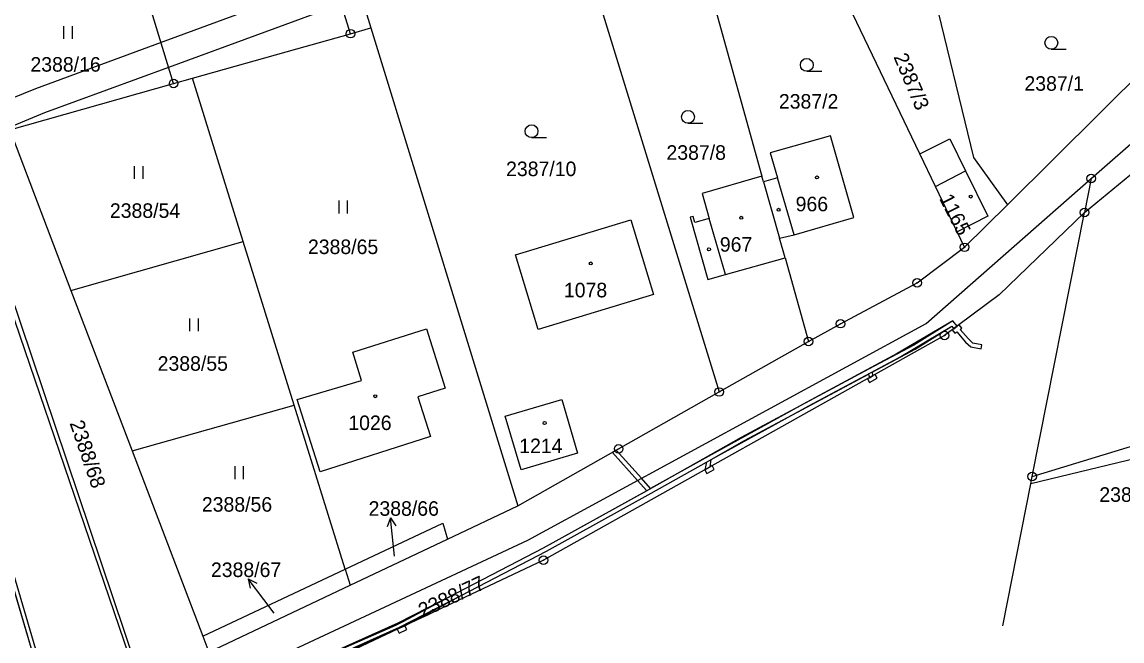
# Model space of a CAD drawing. Extents: x -758836 to -757729, y -1175316 to -1174366.
# Drawn here: x -758454.3 to -758325.7, y -1175183.4 to -1175111 of the extents above; entities that cross this region are included whole.
import ezdxf

# ---------------------------------------------------------------- set-up
doc = ezdxf.new("R2010")
doc.units = 0
for name, color, linetype in [('Hranice parcel', 7, 'Continuous'), ('Parcelní čísla', 7, 'Continuous'), ('Pop  PČ popisy', 7, 'Continuous'), ('Vnitřní kresba', 7, 'Continuous'), ('Věcná břemena k části', 7, 'Continuous'), ('Značky bodu BP', 7, 'Continuous'), ('Značky budov', 7, 'Continuous'), ('Značky kultur', 7, 'Continuous')]:
    doc.layers.add(name, color=color, linetype=linetype)

msp = doc.modelspace()

# ---------------------------------------------------------------- linework, layer by layer
at = {"layer": 'Hranice parcel'}
for p, q in [((-758415.92, -1175112.41), (-758425.55, -1175080.99)), ((-758375.8, -1175100.38), (-758367.83, -1175129.06)), ((-758349.38, -1175126.44), (-758360.76, -1175102.68)), ((-758388.61, -1175102.92), (-758372.81, -1175154.29)), ((-758414.64, -1175108.08), (-758413.52, -1175111.73)), ((-758415.92, -1175112.41), (-758413.52, -1175111.73)), ((-758413.52, -1175111.73), (-758396.34, -1175167.59)), ((-758339.13, -1175132.41), (-758318.22, -1175111.63)), ((-758436.59, -1175118.23), (-758434.39, -1175117.61)), ((-758428.45, -1175136.72), (-758434.39, -1175117.61)), ((-758329.33, -1175129.34), (-758316.55, -1175118.12)), ((-758455.74, -1175123.64), (-758436.59, -1175118.23)), ((-758330.11, -1175133.3), (-758315.7, -1175121.4)), ((-758455.74, -1175123.64), (-758448.59, -1175142.41)), ((-758359.8, -1175124.34), (-758366.84, -1175126.35)), ((-758461.57, -1175125.29), (-758440.3, -1175188.4)), ((-758367.83, -1175129.06), (-758374.82, -1175131.1)), ((-758367.64, -1175129.74), (-758367.83, -1175129.06)), ((-758367.64, -1175129.74), (-758365.77, -1175136.32)), ((-758329.33, -1175129.34), (-758330.11, -1175133.3)), ((-758344.14, -1175137.38), (-758339.13, -1175132.41)), ((-758336.22, -1175164.17), (-758330.11, -1175133.3)), ((-758344.14, -1175137.38), (-758345.01, -1175135.56)), ((-758448.59, -1175142.41), (-758428.45, -1175136.72)), ((-758422.5, -1175155.82), (-758428.45, -1175136.72)), ((-758365.12, -1175138.6), (-758365.77, -1175136.32)), ((-758365.12, -1175138.6), (-758362.37, -1175148.39)), ((-758448.59, -1175142.41), (-758441.44, -1175161.17)), ((-758372.81, -1175154.29), (-758362.37, -1175148.39)), ((-758336.22, -1175164.17), (-758306.97, -1175155.26)), ((-758441.44, -1175161.17), (-758422.5, -1175155.82)), ((-758416.54, -1175174.99), (-758422.5, -1175155.82)), ((-758307.4, -1175158), (-758336.39, -1175165.01)), ((-758441.44, -1175161.17), (-758433.19, -1175182.83)), ((-758336.39, -1175165.01), (-758336.22, -1175164.17)), ((-758339.68, -1175181.63), (-758336.39, -1175165.01)), ((-758404.56, -1175171.48), (-758396.34, -1175167.59)), ((-758415.95, -1175176.88), (-758404.56, -1175171.48)), ((-758433.19, -1175182.83), (-758416.54, -1175174.99)), ((-758416.54, -1175174.99), (-758415.95, -1175176.88)), ((-758432.48, -1175184.7), (-758415.95, -1175176.88)), ((-758433.19, -1175182.83), (-758432.48, -1175184.7))]:
    msp.add_line(p, q, dxfattribs=at)
for points in [[(-758436.59, -1175118.23), (-758442.14, -1175100.06), (-758445.89, -1175087.81)], [(-758347.9, -1175107.11), (-758343.08, -1175126.87), (-758339.13, -1175132.41)], [(-758434.39, -1175117.61), (-758422.18, -1175114.17), (-758415.92, -1175112.41)], [(-758365.77, -1175136.32), (-758364.07, -1175135.91), (-758357.09, -1175133.9), (-758359.8, -1175124.34)], [(-758440.6, -1175188.57), (-758462.14, -1175125.6), (-758461.57, -1175125.29)], [(-758349.38, -1175126.44), (-758345.87, -1175124.7), (-758344.02, -1175128.45), (-758341.4, -1175133.73), (-758345.01, -1175135.56)], [(-758366.84, -1175126.35), (-758366, -1175129.25), (-758367.64, -1175129.74)], [(-758345.01, -1175135.56), (-758347.55, -1175130.26), (-758349.38, -1175126.44)], [(-758452.3, -1175199.04), (-758446.3, -1175195.5), (-758395.2, -1175171.61), (-758348.62, -1175146.28), (-758329.33, -1175129.34)], [(-758374.82, -1175131.1), (-758373.98, -1175134), (-758375.65, -1175134.48), (-758375.86, -1175133.77), (-758376.2, -1175133.86), (-758374.15, -1175141.14), (-758372.09, -1175140.56), (-758365.12, -1175138.6)], [(-758330.11, -1175133.3), (-758340.08, -1175142.92), (-758346.47, -1175147.7), (-758393.35, -1175173.94), (-758437.3, -1175194.73), (-758452.3, -1175199.04)], [(-758380.51, -1175142.9), (-758393.97, -1175146.99), (-758396.61, -1175138.25), (-758383.14, -1175134.16), (-758380.51, -1175142.9)], [(-758362.37, -1175148.39), (-758358.63, -1175146.31), (-758349.68, -1175141.53), (-758344.14, -1175137.38)], [(-758408.05, -1175154.84), (-758406.58, -1175159.49), (-758419.48, -1175163.61), (-758422.14, -1175155.17), (-758414.61, -1175152.93), (-758415.66, -1175149.63), (-758407.02, -1175146.89), (-758404.85, -1175153.83), (-758408.05, -1175154.84)], [(-758389.38, -1175161.44), (-758395.98, -1175163.4), (-758397.84, -1175157.12), (-758391.23, -1175155.18), (-758389.38, -1175161.44)], [(-758396.34, -1175167.59), (-758384.57, -1175160.94), (-758372.81, -1175154.29)], [(-758458.25, -1175167.38), (-758452.99, -1175185.19), (-758456.12, -1175193.18)], [(-758416.54, -1175174.99), (-758405.13, -1175169.62), (-758404.56, -1175171.48)]]:
    msp.add_lwpolyline(points, dxfattribs=at)
at = {"layer": 'Pop  PČ popisy'}
for p, q in [((-758411.22, -1175169.01), (-758411.62, -1175170.05)), ((-758410.91, -1175171.99), (-758411.22, -1175169.01)), ((-758411.22, -1175169.01), (-758410.62, -1175169.95)), ((-758410.77, -1175173.5), (-758410.91, -1175171.99)), ((-758426.06, -1175178.54), (-758427.87, -1175176.14)), ((-758427.87, -1175176.14), (-758426.86, -1175176.64)), ((-758427.87, -1175176.14), (-758427.66, -1175177.24)), ((-758424.83, -1175180.15), (-758426.06, -1175178.54))]:
    msp.add_line(p, q, dxfattribs=at)
at = {"layer": 'Vnitřní kresba'}
for p, q in [((-758347.55, -1175130.26), (-758344.02, -1175128.45)), ((-758364.07, -1175135.91), (-758366, -1175129.25)), ((-758372.09, -1175140.56), (-758373.98, -1175134))]:
    msp.add_line(p, q, dxfattribs=at)
at = {"layer": 'Věcná břemena k části'}
for points in [[(-758456.92, -1175120.55), (-758455.85, -1175123.36), (-758451.64, -1175121.64), (-758437.17, -1175116.34), (-758416.98, -1175108.94), (-758417.89, -1175105.98), (-758438.06, -1175113.43), (-758452.72, -1175118.84)], [(-758344.99, -1175146.59), (-758345.39, -1175146.89), (-758345.59, -1175147.04), (-758345.26, -1175147.43), (-758345.05, -1175147.27), (-758344.01, -1175148.47), (-758343.4, -1175149.03), (-758342.21, -1175149.26), (-758342.11, -1175148.77), (-758343.15, -1175148.57), (-758343.73, -1175148.05), (-758344.66, -1175146.97), (-758344.46, -1175146.82), (-758344.78, -1175146.44)], [(-758354.59, -1175152.25), (-758354.82, -1175152.37), (-758355.26, -1175152.62), (-758355.47, -1175152.74), (-758355.23, -1175153.17), (-758354.35, -1175152.69)], [(-758373.39, -1175163.35), (-758373.63, -1175162.9), (-758373.86, -1175163.03), (-758374.51, -1175163.39), (-758374.27, -1175163.83)], [(-758410.46, -1175182.03), (-758410.24, -1175182.49), (-758409.34, -1175182.05), (-758409.56, -1175181.61)]]:
    msp.add_lwpolyline(points, close=True, dxfattribs=at)
for points in [[(-758452.51, -1175185.05), (-758457.77, -1175167.24), (-758464.65, -1175143.99), (-758470.26, -1175124.61), (-758471.23, -1175121.5), (-758471.28, -1175120.18), (-758472.1, -1175120.53), (-758473.1, -1175120.87), (-758472.98, -1175121.3), (-758472.94, -1175121.45), (-758471.91, -1175121.17), (-758465.13, -1175144.13), (-758458.36, -1175167), (-758459.47, -1175167.31), (-758459.3, -1175167.95), (-758459.26, -1175168.08), (-758458.14, -1175167.76), (-758452.99, -1175185.19)], [(-758426.42, -1175189.06), (-758410.18, -1175181.77), (-758402.97, -1175178.06), (-758393.01, -1175172.91), (-758380.76, -1175166.13), (-758374.3, -1175162.51), (-758373.75, -1175162.2), (-758362.35, -1175155.92), (-758351.76, -1175150.25), (-758345.62, -1175146.61), (-758345.39, -1175146.89), (-758344.99, -1175146.59), (-758345.52, -1175145.97), (-758352, -1175149.81), (-758362.59, -1175155.48), (-758374.1, -1175161.82), (-758380.83, -1175165.59), (-758381.91, -1175164.38), (-758384.85, -1175161.1), (-758385.29, -1175161.35), (-758382.36, -1175164.63), (-758381.28, -1175165.84), (-758393.39, -1175172.55), (-758403.45, -1175177.75), (-758410.4, -1175181.31), (-758426.7, -1175188.64)], [(-758426.42, -1175189.06), (-758410.46, -1175182.03), (-758409.56, -1175181.61), (-758402.97, -1175178.06), (-758393.01, -1175172.91), (-758380.76, -1175166.13), (-758374.3, -1175162.51), (-758374.51, -1175163.39), (-758373.86, -1175163.03), (-758373.75, -1175162.2), (-758369.86, -1175159.96), (-758355.38, -1175152.22), (-758355.26, -1175152.62), (-758354.82, -1175152.37), (-758354.93, -1175151.98), (-758349.9, -1175149.28), (-758345.62, -1175146.61), (-758345.39, -1175146.89), (-758344.99, -1175146.59), (-758345.52, -1175145.97), (-758350.06, -1175148.8), (-758355.35, -1175151.64), (-758370.26, -1175159.6), (-758381, -1175165.69), (-758393.39, -1175172.55), (-758403.45, -1175177.75), (-758409.8, -1175181.17), (-758410.66, -1175181.57), (-758426.7, -1175188.64)]]:
    msp.add_lwpolyline(points, dxfattribs=at)
at = {"layer": 'Značky bodu BP'}
for centre, radius in [((-758415.92, -1175112.41), 0.5), ((-758415.92, -1175112.41), 0.0303), ((-758436.59, -1175118.23), 0.5), ((-758436.59, -1175118.23), 0.0303), ((-758329.33, -1175129.34), 0.5), ((-758329.33, -1175129.34), 0.0303), ((-758330.11, -1175133.3), 0.5), ((-758330.11, -1175133.3), 0.0303), ((-758344.14, -1175137.38), 0.5), ((-758344.14, -1175137.38), 0.0303), ((-758349.68, -1175141.53), 0.5), ((-758349.68, -1175141.53), 0.0303), ((-758358.63, -1175146.31), 0.5), ((-758358.63, -1175146.31), 0.0303), ((-758346.47, -1175147.7), 0.5), ((-758346.47, -1175147.7), 0.0303), ((-758362.37, -1175148.39), 0.5), ((-758362.37, -1175148.39), 0.0303), ((-758372.81, -1175154.29), 0.5), ((-758372.81, -1175154.29), 0.0303), ((-758384.57, -1175160.94), 0.5), ((-758384.57, -1175160.94), 0.0303), ((-758336.22, -1175164.17), 0.5), ((-758336.22, -1175164.17), 0.0303), ((-758393.35, -1175173.94), 0.5), ((-758393.35, -1175173.94), 0.0303)]:
    msp.add_circle(centre, radius, dxfattribs=at)
at = {"layer": 'Značky budov'}
for centre in [(-758361.39, -1175129.21), (-758343.41, -1175131.45), (-758365.88, -1175132.99), (-758370.24, -1175133.93), (-758374.01, -1175137.62), (-758387.83, -1175139.27), (-758413.03, -1175154.78), (-758393.22, -1175157.92)]:
    msp.add_circle(centre, 0.175, dxfattribs=at)
at = {"layer": 'Značky kultur'}
for p, q in [((-758449.41, -1175113.03), (-758449.41, -1175111.53)), ((-758448.41, -1175113.03), (-758448.41, -1175111.53)), ((-758334, -1175114.23), (-758332.25, -1175114.23)), ((-758362.58, -1175116.81), (-758360.83, -1175116.81)), ((-758376.47, -1175122.88), (-758374.72, -1175122.88)), ((-758394.75, -1175124.56), (-758393, -1175124.56)), ((-758441.17, -1175129.38), (-758441.17, -1175127.88)), ((-758440.17, -1175129.38), (-758440.17, -1175127.88)), ((-758417.25, -1175133.42), (-758417.25, -1175131.92)), ((-758416.25, -1175133.42), (-758416.25, -1175131.92)), ((-758434.7, -1175147.2), (-758434.7, -1175145.7)), ((-758433.7, -1175147.2), (-758433.7, -1175145.7)), ((-758429.41, -1175164.47), (-758429.41, -1175162.97)), ((-758428.41, -1175164.47), (-758428.41, -1175162.97))]:
    msp.add_line(p, q, dxfattribs=at)
for centre in [(-758334, -1175113.48), (-758362.58, -1175116.06), (-758376.47, -1175122.13), (-758394.75, -1175123.81)]:
    msp.add_circle(centre, 0.75, dxfattribs=at)

# ---------------------------------------------------------------- texts
at = {"layer": 'Parcelní čísla'}
for s, p in [('2388/16', (-758453.33, -1175116.85)), ('2387/1', (-758337.14, -1175119.08)), ('2387/2', (-758365.84, -1175121.17)), ('2387/8', (-758378.98, -1175127.15)), ('2387/10', (-758397.73, -1175129.06)), ('2388/54', (-758444.04, -1175133.94)), ('966', (-758363.88, -1175133.17)), ('967', (-758372.74, -1175137.89)), ('2388/65', (-758420.89, -1175138.17)), ('1078', (-758390.97, -1175143.23)), ('2388/55', (-758438.46, -1175151.81)), ('1026', (-758416.17, -1175158.74)), ('1214', (-758396.19, -1175161.44)), ('2388/115', (-758328.38, -1175167.13)), ('2388/56', (-758433.29, -1175168.28)), ('2388/66', (-758413.8, -1175168.76)), ('2388/67', (-758432.23, -1175175.92))]:
    msp.add_text(s, height=1.7, dxfattribs=at).set_placement(p)
for s, rotation, p in [('2387/3', 293, (-758352.47, -1175115.11)), ('1165', 297, (-758347.14, -1175131.66)), ('2388/68', 289, (-758448.77, -1175157.93)), ('2388/77', 25, (-758407.49, -1175180.71))]:
    msp.add_text(s, height=1.7, rotation=rotation, dxfattribs=at).set_placement(p)

doc.saveas('drawing.dxf')
